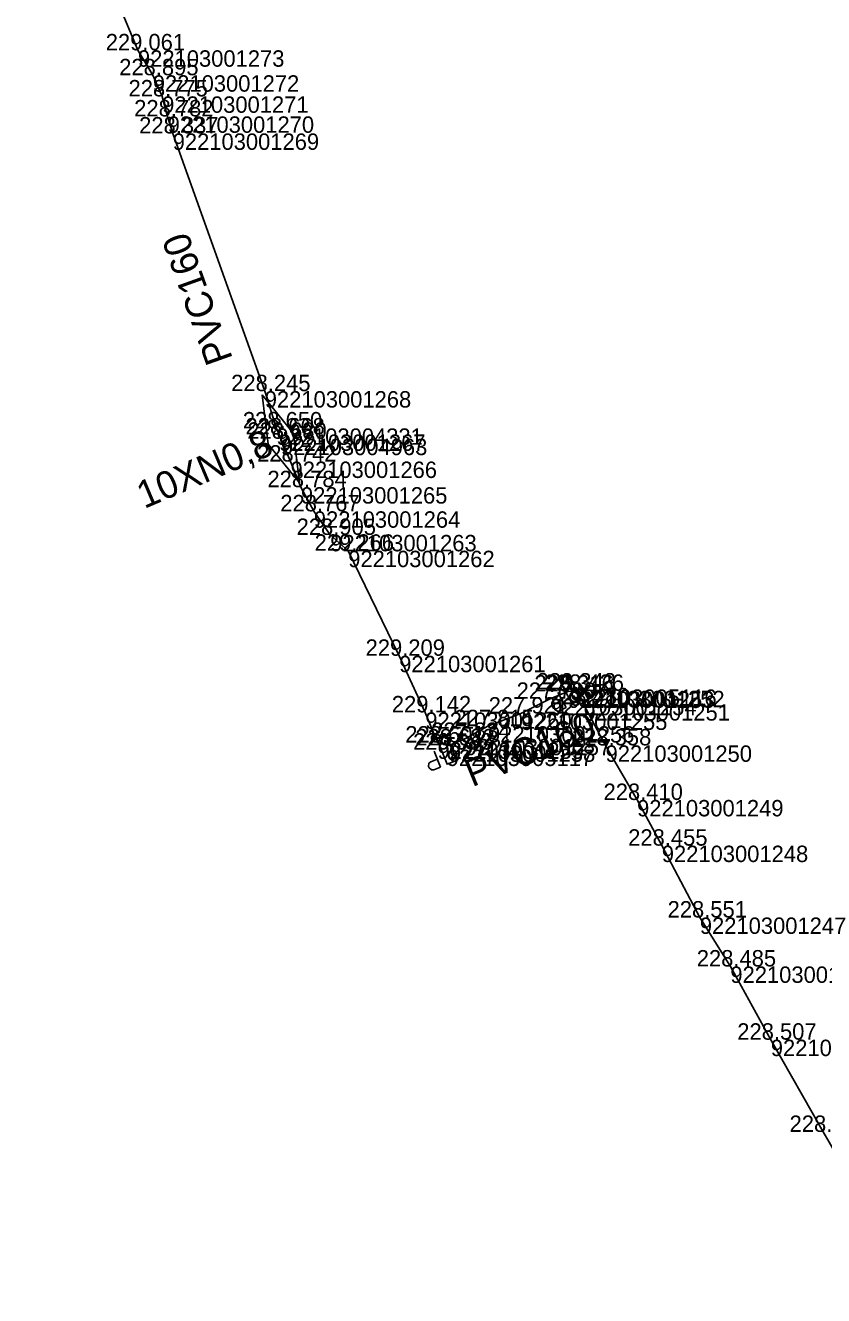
# Model space of a CAD drawing. Extents: x -771047 to -756200, y -1053876 to -1046520.
# Drawn here: x -768846.1 to -768787.7, y -1052726.4 to -1052633.5 of the extents above; entities that cross this region are included whole.
import ezdxf

# ---------------------------------------------------------------- set-up
doc = ezdxf.new("R2010")
doc.units = 0
for name, color, linetype in [('Vrstva 32', 7, 'Continuous'), ('Vrstva 33', 7, 'Continuous'), ('Vrstva 60', 7, 'Continuous'), ('Vrstva 61', 7, 'Continuous')]:
    doc.layers.add(name, color=color, linetype=linetype)

msp = doc.modelspace()

# ---------------------------------------------------------------- linework, layer by layer
at = {"layer": 'Vrstva 32'}
for points in [[(-768836.102, -1052638.7), (-768836.785, -1052637.155), (-768837.868, -1052635.329), (-768839.394, -1052631.684), (-768841.539, -1052626.01), (-768844.739, -1052618.616), (-768846.099, -1052614.879)], [(-768827.551, -1052663.437), (-768827.747, -1052662.994), (-768828.597, -1052660.268), (-768835.331, -1052641.411), (-768835.698, -1052640.164), (-768836.102, -1052638.7)], [(-768828.784, -1052660.528), (-768826.497, -1052663.36), (-768826.052, -1052666.972), (-768828.339, -1052664.14), (-768828.784, -1052660.528)], [(-768823.811, -1052670.788), (-768825.008, -1052669.061), (-768825.95, -1052667.295), (-768826.71, -1052665.421), (-768827.418, -1052663.75), (-768827.551, -1052663.437)], [(-768805.292, -1052683.175), (-768805.679, -1052682.196), (-768806.428, -1052682.242), (-768807.731, -1052682.779), (-768809.864, -1052683.857), (-768812.273, -1052684.782), (-768813.973, -1052685.711), (-768815.137, -1052686.186), (-768815.966, -1052685.977), (-768816.857, -1052683.772), (-768818.768, -1052679.632), (-768822.495, -1052671.944), (-768823.811, -1052670.788)], [(-768780.373, -1052726.447), (-768781.715, -1052724.616), (-768783.017, -1052722.52), (-768784.183, -1052720.645), (-768787.771, -1052714.47), (-768791.593, -1052707.721), (-768794.55, -1052702.364), (-768796.783, -1052698.782), (-768799.565, -1052693.524), (-768801.372, -1052690.182), (-768803.678, -1052686.188), (-768805.292, -1052683.175)]]:
    msp.add_lwpolyline(points, dxfattribs=at)
at = {"layer": 'Vrstva 33'}
for points in [[(-768827.551, -1052663.437), (-768827.747, -1052662.994), (-768828.597, -1052660.268), (-768835.331, -1052641.411), (-768835.698, -1052640.164)], [(-768805.679, -1052682.196), (-768806.428, -1052682.242), (-768807.731, -1052682.779), (-768809.864, -1052683.857), (-768812.273, -1052684.782), (-768813.973, -1052685.711), (-768815.137, -1052686.186), (-768815.966, -1052685.977), (-768816.857, -1052683.772)], [(-768807.167, -1052682.313), (-768806.566, -1052683.414)], [(-768807.023, -1052683.664), (-768807.187, -1052683.693), (-768807.381, -1052683.568), (-768807.434, -1052683.471), (-768807.437, -1052683.236), (-768807.32, -1052683.121)], [(-768807.32, -1052683.121), (-768806.862, -1052682.87)], [(-768806.566, -1052683.414), (-768807.023, -1052683.664)], [(-768816.214, -1052686.608), (-768815.744, -1052687.771)], [(-768816.228, -1052687.966), (-768816.394, -1052687.977), (-768816.572, -1052687.83), (-768816.614, -1052687.728), (-768816.589, -1052687.493), (-768816.459, -1052687.393)], [(-768816.459, -1052687.393), (-768815.976, -1052687.197)], [(-768815.744, -1052687.771), (-768816.228, -1052687.966)]]:
    msp.add_lwpolyline(points, dxfattribs=at)
for points in [[(-768805.456, -1052682.802), (-768806.11, -1052683.159), (-768807.076, -1052681.392), (-768806.422, -1052681.035)], [(-768814.571, -1052687.292), (-768815.262, -1052687.571), (-768816.017, -1052685.704), (-768815.326, -1052685.425)]]:
    msp.add_lwpolyline(points, close=True, dxfattribs=at)
at = {"layer": 'Vrstva 60'}
for p, q in [((-768837.868, -1052635.329), (-768837.868, -1052635.329)), ((-768836.785, -1052637.155), (-768836.785, -1052637.155)), ((-768836.102, -1052638.7), (-768836.102, -1052638.7)), ((-768835.698, -1052640.164), (-768835.698, -1052640.164)), ((-768835.331, -1052641.411), (-768835.331, -1052641.411)), ((-768828.597, -1052660.268), (-768828.597, -1052660.268)), ((-768827.747, -1052662.994), (-768827.747, -1052662.994)), ((-768827.551, -1052663.437), (-768827.551, -1052663.437)), ((-768827.418, -1052663.75), (-768827.418, -1052663.75)), ((-768826.71, -1052665.421), (-768826.71, -1052665.421)), ((-768825.95, -1052667.295), (-768825.95, -1052667.295)), ((-768825.008, -1052669.061), (-768825.008, -1052669.061)), ((-768823.811, -1052670.788), (-768823.811, -1052670.788)), ((-768822.495, -1052671.944), (-768822.495, -1052671.944)), ((-768818.768, -1052679.632), (-768818.768, -1052679.632)), ((-768806.428, -1052682.242), (-768806.428, -1052682.242)), ((-768806.266, -1052682.097), (-768806.266, -1052682.097)), ((-768805.679, -1052682.196), (-768805.679, -1052682.196)), ((-768807.731, -1052682.779), (-768807.731, -1052682.779)), ((-768805.292, -1052683.175), (-768805.292, -1052683.175)), ((-768816.857, -1052683.772), (-768816.857, -1052683.772)), ((-768809.864, -1052683.857), (-768809.864, -1052683.857)), ((-768812.273, -1052684.782), (-768812.273, -1052684.782)), ((-768815.966, -1052685.977), (-768815.966, -1052685.977)), ((-768813.973, -1052685.711), (-768813.973, -1052685.711)), ((-768815.294, -1052686.498), (-768815.294, -1052686.498)), ((-768815.137, -1052686.186), (-768815.137, -1052686.186)), ((-768803.678, -1052686.188), (-768803.678, -1052686.188)), ((-768801.372, -1052690.182), (-768801.372, -1052690.182)), ((-768799.565, -1052693.524), (-768799.565, -1052693.524)), ((-768796.783, -1052698.782), (-768796.783, -1052698.782)), ((-768794.55, -1052702.364), (-768794.55, -1052702.364)), ((-768791.593, -1052707.721), (-768791.593, -1052707.721)), ((-768787.771, -1052714.47), (-768787.771, -1052714.47))]:
    msp.add_line(p, q, dxfattribs=at)

# ---------------------------------------------------------------- texts
at = {"layer": 'Vrstva 32'}
msp.add_text('10XN0,8', height=2, rotation=22.97166, dxfattribs=at).set_placement((-768837.41, -1052668.893))
at = {"layer": 'Vrstva 33'}
for rotation, p in [(109.65209, (-768830.915, -1052657.892)), (22.19917, (-768813.433, -1052689.254))]:
    msp.add_text('PVC160', height=2, rotation=rotation, dxfattribs=at).set_placement(p)
at = {"layer": 'Vrstva 60'}
for s, p in [('922103001273', (-768837.868, -1052636.529)), ('922103001272', (-768836.785, -1052638.355)), ('922103001271', (-768836.102, -1052639.9)), ('922103001270', (-768835.698, -1052641.364)), ('922103001269', (-768835.331, -1052642.611)), ('922103001268', (-768828.597, -1052661.468)), ('922103004331', (-768827.747, -1052664.194)), ('922103001267', (-768827.551, -1052664.637)), ('922103004963', (-768827.418, -1052664.95)), ('922103001266', (-768826.71, -1052666.621)), ('922103001265', (-768825.95, -1052668.495)), ('922103001264', (-768825.008, -1052670.261)), ('922103001263', (-768823.811, -1052671.988)), ('922103001262', (-768822.495, -1052673.144)), ('922103001261', (-768818.768, -1052680.832)), ('922103001253', (-768806.428, -1052683.442)), ('922103005116', (-768806.266, -1052683.297)), ('922103001252', (-768805.679, -1052683.396)), ('922103001254', (-768807.731, -1052683.979)), ('922103001251', (-768805.292, -1052684.375)), ('922103001260', (-768816.857, -1052684.972)), ('922103001255', (-768809.864, -1052685.057)), ('922103001256', (-768812.273, -1052685.982)), ('922103001259', (-768815.966, -1052687.177)), ('922103001257', (-768813.973, -1052686.911)), ('922103005117', (-768815.294, -1052687.698)), ('922103001258', (-768815.137, -1052687.386)), ('922103001250', (-768803.678, -1052687.388)), ('922103001249', (-768801.372, -1052691.382)), ('922103001248', (-768799.565, -1052694.724)), ('922103001247', (-768796.783, -1052699.982)), ('922103001246', (-768794.55, -1052703.564)), ('922103001245', (-768791.593, -1052708.921))]:
    msp.add_text(s, height=1.2, dxfattribs=at).set_placement(p)
at = {"layer": 'Vrstva 61'}
for s, p in [('229.061', (-768840.225, -1052635.329)), ('228.895', (-768839.241, -1052637.155)), ('228.775', (-768838.558, -1052638.7)), ('228.782', (-768838.146, -1052640.164)), ('228.337', (-768837.783, -1052641.411)), ('228.245', (-768831.053, -1052660.268)), ('228.650', (-768830.198, -1052662.994)), ('228.668', (-768830.005, -1052663.437)), ('228.680', (-768829.869, -1052663.75)), ('228.742', (-768829.158, -1052665.421)), ('228.784', (-768828.401, -1052667.295)), ('228.767', (-768827.46, -1052669.061)), ('228.905', (-768826.267, -1052670.788)), ('229.266', (-768824.947, -1052671.944)), ('229.209', (-768821.222, -1052679.632)), ('228.316', (-768808.88, -1052682.242)), ('229.343', (-768808.718, -1052682.097)), ('228.426', (-768808.131, -1052682.196)), ('227.790', (-768810.182, -1052682.779)), ('228.480', (-768807.743, -1052683.175)), ('229.142', (-768819.305, -1052683.772)), ('227.921', (-768812.221, -1052683.857)), ('227.815', (-768814.729, -1052684.782)), ('228.601', (-768818.323, -1052685.977)), ('228.682', (-768817.585, -1052686.186)), ('227.834', (-768816.424, -1052685.711)), ('228.358', (-768806.132, -1052686.188)), ('229.583', (-768817.746, -1052686.498)), ('228.410', (-768803.823, -1052690.182)), ('228.455', (-768802.021, -1052693.524)), ('228.551', (-768799.14, -1052698.782)), ('228.485', (-768797.006, -1052702.364)), ('228.507', (-768794.045, -1052707.721)), ('228.582', (-768790.219, -1052714.47))]:
    msp.add_text(s, height=1.2, dxfattribs=at).set_placement(p)

doc.saveas('drawing.dxf')
